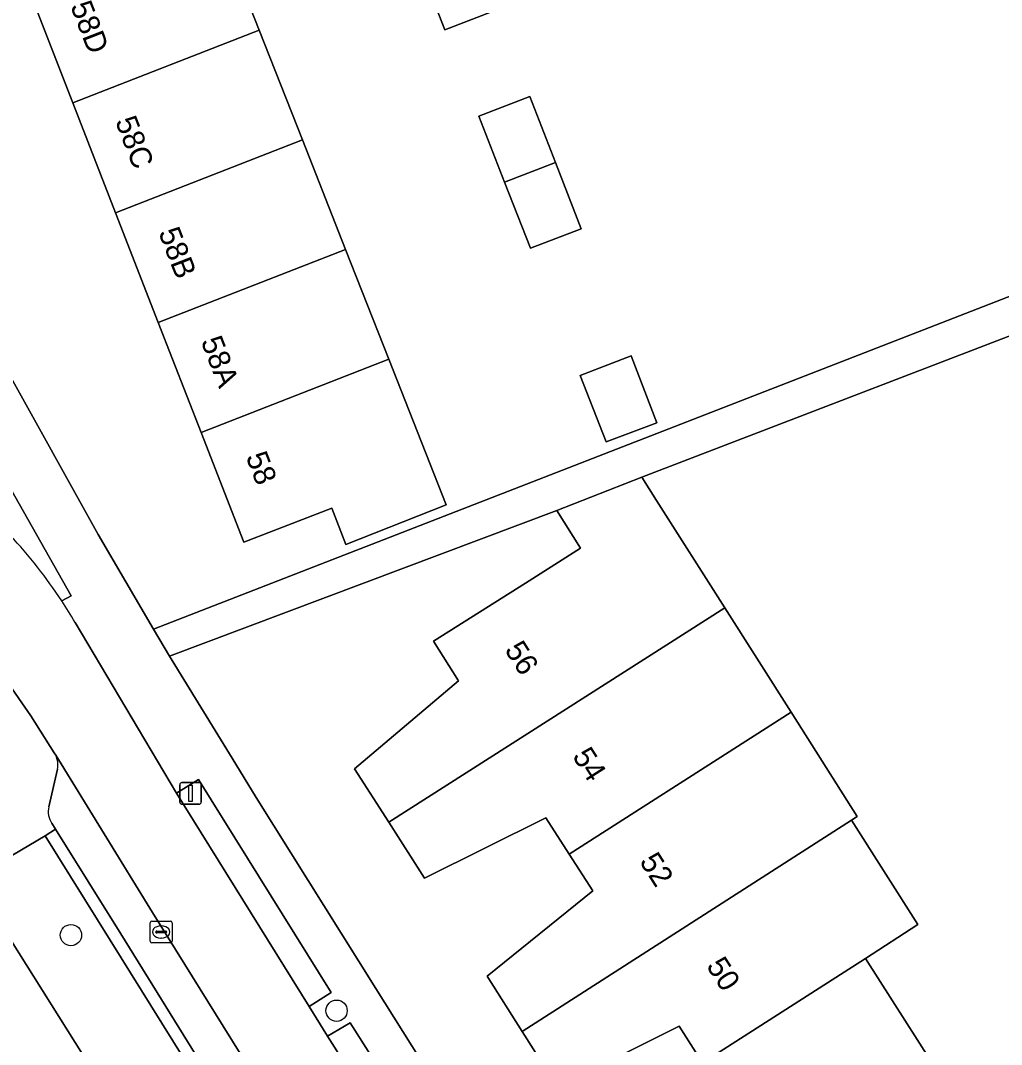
# Model space of a CAD drawing. Extents: x 159680 to 160786, y 387323 to 388340.
# Drawn here: x 159845.54 to 159890.67, y 387693.25 to 387740.35 of the extents above; entities that cross this region are included whole.
import ezdxf

# ---------------------------------------------------------------- set-up
doc = ezdxf.new("R2010")
doc.units = 0
for name, color, linetype in [('IMGEO_Berm_groen', 7, 'Continuous'), ('IMGEO_Boom', 7, 'Continuous'), ('IMGEO_Erf', 7, 'Continuous'), ('IMGEO_Fietspad_gesloten', 7, 'Continuous'), ('IMGEO_Kolk', 7, 'Continuous'), ('IMGEO_Lichtmast', 7, 'Continuous'), ('IMGEO_Pand', 7, 'Continuous'), ('IMGEO_Pand_nummerreeks', 7, 'Continuous'), ('IMGEO_Rijbaan_regionaal_gesloten', 7, 'Continuous'), ('IMGEO_Voetpad_open', 7, 'Continuous')]:
    doc.layers.add(name, color=color, linetype=linetype)

msp = doc.modelspace()

# ---------------------------------------------------------------- linework, layer by layer
at = {"layer": 'IMGEO_Berm_groen'}
for points in [[(159847.442, 387713.648), (159847.883, 387713.881), (159836.437, 387734.091), (159823.476, 387757.109)], [(159846.024, 387708.36), (159844.89, 387710.006), (159843.949, 387711.365), (159843.096, 387712.46)], [(159847.165, 387706.549), (159847.089, 387706.656), (159846.024, 387708.36)], [(159846.855, 387704.18), (159847.242, 387705.904)], [(159843.321, 387700.86), (159846.674, 387702.849), (159847.154, 387703.149), (159846.986, 387703.419)], [(159854.423, 387690.403), (159849.673, 387698.047), (159846.674, 387702.849), (159843.321, 387700.86), (159843.801, 387700.086), (159844.283, 387699.312), (159848.808, 387692.139), (159854.91, 387682.508), (159859.345, 387675.48), (159862.656, 387670.301), (159870.936, 387657.259), (159881.358, 387640.862), (159893.876, 387621.079), (159895.607, 387618.335)]]:
    msp.add_lwpolyline(points, dxfattribs=at)
for centre, radius, start, end in [((159828.486, 387701.206), 22.674, 33.2786, 42.9923), ((159846.23, 387706.11), 1.033, 348.4813, 25.1342), ((159847.745, 387703.941), 0.921, 164.9837, 214.5508)]:
    msp.add_arc(centre, radius, start, end, dxfattribs=at)
at = {"layer": 'IMGEO_Boom'}
for centre in [(159847.866, 387698.276), (159860.084, 387694.8)]:
    msp.add_circle(centre, 0.489, dxfattribs=at)
at = {"layer": 'IMGEO_Erf'}
for points in [[(159866.279, 387743.737), (159867.412, 387740.826), (159865.065, 387739.914), (159863.934, 387742.823), (159862.799, 387745.743), (159865.145, 387746.647)], [(159871.339, 387730.769), (159868.998, 387729.867), (159867.814, 387732.904), (159866.626, 387735.95), (159868.977, 387736.857), (159870.158, 387733.813)], [(159874.819, 387721.84), (159872.487, 387720.967), (159871.288, 387724.017), (159873.632, 387724.923)]]:
    msp.add_lwpolyline(points, close=True, dxfattribs=at)
for points in [[(159832.352, 387746.607), (159840.566, 387732.077), (159849.124, 387716.699), (159851.67, 387712.351), (159896.117, 387729.631)], [(159854.395, 387745.324), (159856.53, 387739.898), (159858.516, 387734.853), (159860.501, 387729.808), (159862.487, 387724.763), (159865.122, 387718.066), (159860.517, 387716.247), (159859.87, 387717.921), (159855.819, 387716.349), (159853.852, 387721.401), (159851.885, 387726.453), (159849.918, 387731.506), (159847.951, 387736.558), (159845.984, 387741.61)], [(159895.611, 387727.591), (159874.13, 387719.335), (159874.801, 387718.273), (159877.941, 387713.332), (159880.989, 387708.536), (159884.037, 387703.74), (159883.776, 387703.572), (159886.829, 387698.769), (159884.414, 387697.206), (159887.459, 387692.416), (159890.5, 387687.61), (159890.587, 387687.493), (159891.744, 387688.24)], [(159876.921, 387692.41), (159875.846, 387694.095), (159870.254, 387691.281), (159868.623, 387693.851), (159867.015, 387696.384), (159871.866, 387700.321), (159870.78, 387702.008), (159869.706, 387703.677), (159864.128, 387700.901), (159862.483, 387703.474), (159860.913, 387705.929), (159865.689, 387709.968), (159864.547, 387711.792), (159868.774, 387714.465), (159871.309, 387716.068), (159870.209, 387717.81), (159852.398, 387711.107), (159855.275, 387706.413), (159856.385, 387704.612), (159861.884, 387695.822), (159866.365, 387688.698)]]:
    msp.add_lwpolyline(points, dxfattribs=at)
at = {"layer": 'IMGEO_Fietspad_gesloten'}
for points in [[(159843.096, 387712.46), (159843.949, 387711.365), (159844.89, 387710.006), (159846.024, 387708.36), (159847.089, 387706.656), (159847.165, 387706.549), (159851.617, 387699.318), (159856.363, 387691.703)], [(159883.934, 387655.5), (159883.122, 387656.732), (159871.809, 387674.544), (159870.938, 387675.892), (159859.674, 387693.624), (159858.823, 387694.997), (159852.727, 387704.808), (159848.054, 387712.66)]]:
    msp.add_lwpolyline(points, dxfattribs=at)
for centre, radius, start, end in [((159828.486, 387701.206), 22.674, 33.2786, 42.9923), ((159827.836, 387700.82), 23.43, 30.3543, 33.1966)]:
    msp.add_arc(centre, radius, start, end, dxfattribs=at)
at = {"layer": 'IMGEO_Kolk'}
for p, q in [((159851.515, 387697.996), (159851.515, 387698.848)), ((159851.59, 387698.922), (159852.442, 387698.922)), ((159852.003, 387698.702), (159852.028, 387698.702)), ((159852.516, 387698.848), (159852.516, 387697.996)), ((159851.774, 387698.416), (159851.774, 387698.428)), ((159852.212, 387698.379), (159851.814, 387698.379)), ((159851.817, 387698.465), (159852.215, 387698.465)), ((159852.026, 387698.142), (159852.001, 387698.142)), ((159852.258, 387698.428), (159852.258, 387698.416)), ((159852.442, 387697.922), (159851.59, 387697.922))]:
    msp.add_line(p, q, dxfattribs=at)
for points in [[(159851.515, 387697.996), (159851.515, 387698.848)], [(159851.59, 387698.922), (159852.442, 387698.922)], [(159852.516, 387698.848), (159852.516, 387697.996)], [(159852.442, 387697.922), (159851.59, 387697.922)]]:
    msp.add_lwpolyline(points, dxfattribs=at)
for centre, radius, start, end in [((159851.592, 387698.846), 0.0765, 91.552, 178.448), ((159851.592, 387698.846), 0.0765, 91.552, 178.448), ((159852.44, 387698.846), 0.0765, 1.552, 88.448), ((159852.44, 387698.846), 0.0765, 1.552, 88.448), ((159851.814, 387698.425), 0.0403, 85.8775, 175.7526), ((159851.811, 387698.415), 0.0366, 178.938, 274.7102), ((159852.215, 387698.422), 0.043, 264.8664, 352.4533), ((159852.219, 387698.427), 0.0386, 1.7309, 96.639), ((159851.592, 387697.998), 0.0765, 181.552, 268.448), ((159851.592, 387697.998), 0.0765, 181.552, 268.448), ((159852.44, 387697.998), 0.0765, 271.552, 358.448), ((159852.44, 387697.998), 0.0765, 271.552, 358.448)]:
    msp.add_arc(centre, radius, start, end, dxfattribs=at)
for centre, major_axis, ratio, start_param, end_param in [((159852.002, 387698.422), (-0.387, 0.002), 0.722429, 4.712389, 7.853982), ((159852.027, 387698.422), (-0.39, 0.002), 0.717154, 1.570796, 4.712389)]:
    msp.add_ellipse(centre, major_axis=major_axis, ratio=ratio, start_param=start_param, end_param=end_param, dxfattribs=at)
at = {"layer": 'IMGEO_Lichtmast'}
for p, q in [((159852.869, 387704.397), (159852.869, 387705.197)), ((159852.869, 387705.197), (159852.869, 387704.397)), ((159852.969, 387705.297), (159853.759, 387705.297)), ((159853.759, 387705.297), (159852.969, 387705.297)), ((159853.859, 387705.197), (159853.859, 387704.397)), ((159853.859, 387704.397), (159853.859, 387705.197)), ((159853.759, 387704.297), (159852.969, 387704.297)), ((159852.969, 387704.297), (159853.759, 387704.297))]:
    msp.add_line(p, q, dxfattribs=at)
msp.add_lwpolyline([(159853.289, 387705.172), (159853.439, 387705.172), (159853.439, 387704.422), (159853.289, 387704.422), (159853.289, 387705.172)], dxfattribs=at)
for centre, start, end in [((159852.969, 387705.197), 90, 180), ((159852.969, 387705.197), 90, 180), ((159853.759, 387705.197), 0, 90), ((159853.759, 387705.197), 360, 90), ((159852.969, 387704.397), 180, 270), ((159852.969, 387704.397), 180, 270), ((159853.759, 387704.397), 270, 0), ((159853.759, 387704.397), 270, 0)]:
    msp.add_arc(centre, 0.1, start, end, dxfattribs=at)
at = {"layer": 'IMGEO_Pand'}
for points in [[(159854.395, 387745.324), (159851.355, 387744.148), (159845.828, 387742.01), (159845.844, 387741.969), (159845.984, 387741.61), (159847.951, 387736.558), (159856.53, 387739.898)], [(159866.279, 387743.737), (159863.934, 387742.823), (159865.065, 387739.914), (159867.412, 387740.826)], [(159856.53, 387739.898), (159847.951, 387736.558), (159849.918, 387731.506), (159858.516, 387734.853)], [(159868.977, 387736.857), (159866.626, 387735.95), (159867.814, 387732.904), (159870.158, 387733.813)], [(159858.516, 387734.853), (159849.918, 387731.506), (159851.885, 387726.453), (159860.501, 387729.808)], [(159870.158, 387733.813), (159867.814, 387732.904), (159868.998, 387729.867), (159871.339, 387730.769)], [(159860.501, 387729.808), (159851.885, 387726.453), (159853.852, 387721.401), (159862.487, 387724.763)], [(159862.487, 387724.763), (159853.852, 387721.401), (159855.819, 387716.349), (159859.87, 387717.921), (159860.517, 387716.247), (159865.122, 387718.066)], [(159873.632, 387724.923), (159871.288, 387724.017), (159872.487, 387720.967), (159874.819, 387721.84)], [(159877.941, 387713.332), (159874.801, 387718.273), (159874.13, 387719.335), (159870.209, 387717.81), (159871.309, 387716.068), (159868.774, 387714.465), (159864.547, 387711.792), (159865.689, 387709.968), (159860.913, 387705.929), (159862.483, 387703.474)], [(159862.483, 387703.474), (159864.128, 387700.901), (159869.706, 387703.677), (159870.78, 387702.008), (159880.989, 387708.536), (159877.941, 387713.332)], [(159883.776, 387703.572), (159884.037, 387703.74), (159880.989, 387708.536), (159870.78, 387702.008), (159871.866, 387700.321), (159867.015, 387696.384), (159868.623, 387693.851)], [(159884.414, 387697.206), (159886.829, 387698.769), (159883.776, 387703.572), (159868.623, 387693.851), (159870.254, 387691.281), (159875.846, 387694.095), (159876.921, 387692.41)], [(159887.459, 387692.416), (159884.414, 387697.206), (159876.921, 387692.41), (159877.98, 387690.752), (159873.091, 387686.828), (159874.708, 387684.237)]]:
    msp.add_lwpolyline(points, close=True, dxfattribs=at)
at = {"layer": 'IMGEO_Rijbaan_regionaal_gesloten'}
msp.add_lwpolyline([(159895.607, 387618.335), (159893.876, 387621.079), (159881.358, 387640.862), (159870.936, 387657.259), (159862.656, 387670.301), (159859.345, 387675.48), (159854.91, 387682.508), (159848.808, 387692.139), (159844.283, 387699.312), (159843.801, 387700.086), (159843.321, 387700.86)], dxfattribs=at)
at = {"layer": 'IMGEO_Voetpad_open'}
for points in [[(159866.365, 387688.698), (159861.884, 387695.822), (159856.385, 387704.612), (159855.275, 387706.413), (159852.398, 387711.107), (159851.67, 387712.351), (159849.124, 387716.699), (159840.566, 387732.077), (159832.352, 387746.607), (159825.014, 387759.589), (159823.476, 387757.109), (159836.437, 387734.091), (159847.883, 387713.881), (159847.442, 387713.648)], [(159848.054, 387712.66), (159852.727, 387704.808), (159853.74, 387705.441), (159859.84, 387695.634), (159858.823, 387694.997), (159859.674, 387693.624), (159860.716, 387694.25), (159871.963, 387676.542), (159870.938, 387675.892), (159871.809, 387674.544), (159872.831, 387675.167), (159884.166, 387657.358), (159883.122, 387656.732), (159883.934, 387655.5), (159884.972, 387656.109), (159896.483, 387637.94)], [(159856.363, 387691.703), (159851.617, 387699.318), (159847.165, 387706.549)], [(159847.242, 387705.904), (159846.855, 387704.18)], [(159846.986, 387703.419), (159847.154, 387703.149), (159850.155, 387698.334), (159854.906, 387690.684)], [(159854.906, 387690.684), (159850.155, 387698.334), (159847.154, 387703.149), (159846.674, 387702.849), (159849.673, 387698.047), (159854.423, 387690.403)]]:
    msp.add_lwpolyline(points, dxfattribs=at)
for points in [[(159896.117, 387729.631), (159851.67, 387712.351), (159852.398, 387711.107), (159870.209, 387717.81), (159874.13, 387719.335), (159895.611, 387727.591), (159896.855, 387725.323), (159903.29, 387712.78), (159904.832, 387710.171), (159907.661, 387705.382), (159907.495, 387705.284), (159911.171, 387697.827), (159912.652, 387694.968), (159913.046, 387694.426), (159913.137, 387694.469), (159915.547, 387689.468), (159918.01, 387684.569), (159920.552, 387679.737), (159923.596, 387674.886), (159923.707, 387674.709), (159924.469, 387675.163)], [(159852.727, 387704.808), (159858.823, 387694.997), (159859.84, 387695.634), (159853.74, 387705.441)], [(159859.674, 387693.624), (159870.938, 387675.892), (159871.963, 387676.542), (159860.716, 387694.25)]]:
    msp.add_lwpolyline(points, close=True, dxfattribs=at)
for centre, radius, start, end in [((159827.836, 387700.82), 23.43, 30.3543, 33.1966), ((159846.23, 387706.11), 1.033, 348.4813, 25.1342), ((159847.745, 387703.941), 0.921, 164.9837, 214.5508)]:
    msp.add_arc(centre, radius, start, end, dxfattribs=at)

# ---------------------------------------------------------------- texts
at = {"layer": 'IMGEO_Pand_nummerreeks'}
for s, rotation, p in [('58D', 291.2737, (159847.826, 387741.013)), ('58C', 291.2737, (159849.888, 387735.716)), ('58B', 291.2737, (159851.879, 387730.602)), ('58A', 291.2737, (159853.828, 387725.595)), ('58', 291.2737, (159855.897, 387720.283)), ('56', 302.5005, (159867.787, 387711.397)), ('54', 302.5005, (159870.904, 387706.505)), ('52', 302.6125, (159873.991, 387701.664)), ('50', 302.6125, (159877.065, 387696.861))]:
    msp.add_text(s, height=1, rotation=rotation, dxfattribs=at).set_placement(p)

doc.saveas('drawing.dxf')
